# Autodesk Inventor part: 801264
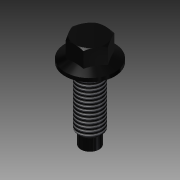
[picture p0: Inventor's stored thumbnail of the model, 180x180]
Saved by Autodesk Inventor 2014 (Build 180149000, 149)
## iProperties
Created: 2007-11
Part Number: 801264
Document SubType Name: Modeling
Designer: TH
Density: 7.85 g/cm^3
Mass: 31.545 g
Surface Area: 19.7101 cm^2
Volume: 4.01847 cm^3
Material: Steel
Description: R23423 - M12 x 16
Appearance: Glossy - Black
Component Category: Fasteners
Author: TH
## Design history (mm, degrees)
sketch "Sketch1"
  geometry: L1 (-10.508, 0)-(10.508, 0) reference; L2 (7.506, 0)-(3.753, -6.5); L3 (3.753, -6.5)-(-3.753, -6.5); L4 (-3.753, -6.5)-(-7.506, 0); L5 (-7.506, 0)-(-3.753, 6.5); L6 (-3.753, 6.5)-(3.753, 6.5); L7 (3.753, 6.5)-(7.506, 0); 2 further points
  constraints: 12 end point, 1 coincident, 1 point on line, 13 other
  dimensions: "d0" = 13 distance between parallel lines of L3 L6
extrude "Extrusion1" new body sketch "Sketch1" distance "d1" = 9.7; taper "d2" = 0 deg
sketch "Sketch2"
  geometry: L1 (3.753, -9.7)-(-3.753, -9.7) reference; L2 (7.506, -9.7)-(3.753, -9.7) reference; L3 (3.753, -9.7)-(7.506, -9.7) reference; L4 (-3.753, -9.7)-(3.753, -9.7) reference; L5 (-7.506, -9.7)-(-3.753, -9.7) reference; L6 (-3.753, -9.7)-(-7.506, -9.7) reference; L7 (0, -9.7)-(-10.4, -9.7); L8 (-10.4, -9.7)-(-10.4, -8.2); L9 (-10.4, -8.2)-(0, -3.892); L10 (0, -3.892)-(0, -9.7); L11 (-5, -9.7)-(-5, -33.55); L12 (-5, -33.55)-(-3.85, -34.7); L13 (-3.85, -34.7)-(-3.85, -39.7); L14 (-3.85, -39.7)-(0, -39.7); L15 (0, -9.7)-(0, -39.7); 1 further point
  constraints: 18 end point, 4 perpendicular, 2 parallel, 2 point on line, 1 midpoint
  dimensions: "d3" = 1.5 distance of L7.end L8.end; "d4" = 10.4 distance of L7.start L7.end; "d5" = 22.5 deg angle of L7 L9; "d7" = 5 distance between parallel lines of L15 L11; "d8" = 3.85 distance between parallel lines of L15 L13; "d9" = 30 distance between parallel lines of L7 L14; "d10" = 5 distance from line of L12.end L14; "d11" = 1.15 horizontal distance of L11.end L12.end
revolve "Revolution1" sketch "Sketch2" stored, may be unused: angle "d12" = 90 deg
sketch "Sketch3"
  geometry: L1 (-6.5, 0)-(-7.506, -0.581); L2 (-7.506, -0.581)-(-7.506, 0); L3 (-7.506, 0)-(-6.5, 0); L4 (0, -0.697)-(0, 0.116) reference; 1 further point
  constraints: 6 end point, 1 perpendicular, 1 point on line, 1 vertical
  dimensions: "d13" = 30 deg angle of L1 L3; "d14" = 1.00555 distance of L2.end L1.start; "d16" = 6.5 distance of L1.start point (0, 0)
revolve "Revolution2" sketch "Sketch3" stored, may be unused: angle "d17" = 90 deg
thread "Thread1" dims "d18" = 10, "d19" = 0
fillet "Fillet1" dims "d20" = 0.2
body "Solid1"
node "Projected Loop1"
